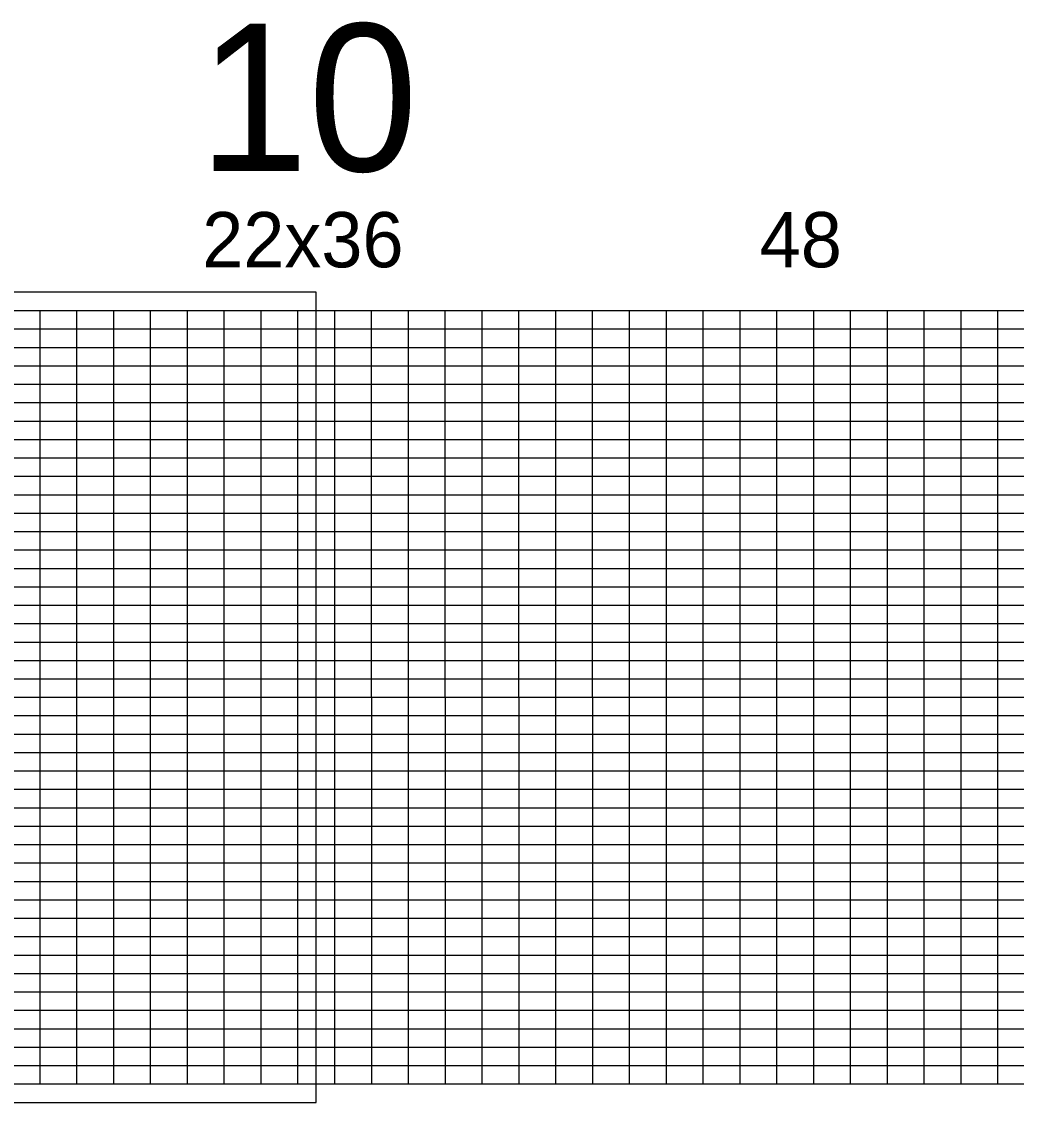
# Model space of a CAD drawing. Extents: x 1870112 to 1888282, y 758439 to 777406.
# Drawn here: x 1884257 to 1885607, y 758439 to 759906 of the extents above; entities that cross this region are included whole.
import ezdxf

# ---------------------------------------------------------------- set-up
doc = ezdxf.new("R2010")
doc.units = 0
for name, color, linetype in [('RD_PD_WallFill', 7, 'Continuous'), ('RD_SHT_IplotShp', 7, 'Continuous'), ('RD_Sketch8', 7, 'Continuous')]:
    doc.layers.add(name, color=color, linetype=linetype)

msp = doc.modelspace()

# ---------------------------------------------------------------- linework, layer by layer
at = {"layer": 'RD_PD_WallFill'}
for p, q in [((1882931.6, 759514.2), (1888281.6, 759514.2)), ((1882931.6, 759514.2), (1884681.6, 759514.2)), ((1884281.6, 758464.2), (1884281.6, 759514.2)), ((1884281.6, 758464.2), (1884281.6, 759514.2)), ((1884331.7, 758464.2), (1884331.6, 759514.2)), ((1884331.7, 758464.2), (1884331.6, 759514.2)), ((1884381.7, 758464.2), (1884381.6, 759514.2)), ((1884381.7, 758464.2), (1884381.6, 759514.2)), ((1884431.6, 758464.2), (1884431.7, 759514.2)), ((1884431.6, 758464.2), (1884431.7, 759514.2)), ((1884481.6, 758464.2), (1884481.6, 759514.2)), ((1884481.6, 758464.2), (1884481.6, 759514.2)), ((1884531.7, 758464.2), (1884531.6, 759514.2)), ((1884531.7, 758464.2), (1884531.6, 759514.2)), ((1884581.6, 758464.2), (1884581.7, 759514.2)), ((1884581.6, 758464.2), (1884581.7, 759514.2)), ((1884631.6, 758464.2), (1884631.7, 759514.2)), ((1884631.6, 758464.2), (1884631.7, 759514.2)), ((1884681.7, 758464.2), (1884681.6, 759514.2)), ((1884681.7, 758464.2), (1884681.6, 759514.2)), ((1884731.7, 758464.2), (1884731.6, 759514.2)), ((1884731.7, 758464.2), (1884731.6, 759514.2)), ((1884781.7, 758464.2), (1884781.6, 759514.2)), ((1884781.7, 758464.2), (1884781.6, 759514.2)), ((1884831.7, 758464.2), (1884831.6, 759514.2)), ((1884831.7, 758464.2), (1884831.6, 759514.2)), ((1884881.7, 758464.2), (1884881.6, 759514.2)), ((1884881.7, 758464.2), (1884881.6, 759514.2)), ((1884931.7, 758464.2), (1884931.6, 759514.2)), ((1884931.7, 758464.2), (1884931.6, 759514.2)), ((1884981.7, 758464.2), (1884981.6, 759514.2)), ((1884981.7, 758464.2), (1884981.6, 759514.2)), ((1885031.7, 758464.2), (1885031.6, 759514.2)), ((1885031.7, 758464.2), (1885031.6, 759514.2)), ((1885081.7, 758464.2), (1885081.6, 759514.2)), ((1885081.7, 758464.2), (1885081.6, 759514.2)), ((1885131.7, 758464.2), (1885131.6, 759514.2)), ((1885131.7, 758464.2), (1885131.6, 759514.2)), ((1885181.7, 758464.2), (1885181.6, 759514.2)), ((1885181.7, 758464.2), (1885181.6, 759514.2)), ((1885231.7, 758464.2), (1885231.6, 759514.2)), ((1885231.7, 758464.2), (1885231.6, 759514.2)), ((1885281.7, 758464.2), (1885281.6, 759514.2)), ((1885281.7, 758464.2), (1885281.6, 759514.2)), ((1885331.7, 758464.2), (1885331.6, 759514.2)), ((1885331.7, 758464.2), (1885331.6, 759514.2)), ((1885381.7, 758464.2), (1885381.6, 759514.2)), ((1885381.7, 758464.2), (1885381.6, 759514.2)), ((1885431.7, 758464.2), (1885431.6, 759514.2)), ((1885431.7, 758464.2), (1885431.6, 759514.2)), ((1885481.7, 758464.2), (1885481.6, 759514.2)), ((1885481.7, 758464.2), (1885481.6, 759514.2)), ((1885531.7, 758464.2), (1885531.6, 759514.2)), ((1885531.7, 758464.2), (1885531.6, 759514.2)), ((1885581.7, 758464.2), (1885581.6, 759514.2)), ((1885581.7, 758464.2), (1885581.6, 759514.2)), ((1883381.6, 759489.2), (1888281.6, 759489.2)), ((1883381.6, 759489.2), (1888281.6, 759489.2)), ((1883381.6, 759464.2), (1888281.6, 759464.2)), ((1883381.6, 759439.2), (1888281.6, 759439.2)), ((1883381.6, 759414.2), (1888281.6, 759414.2)), ((1883381.6, 759389.2), (1888281.6, 759389.2)), ((1882931.6, 759364.2), (1888281.6, 759364.2)), ((1882931.6, 759339.2), (1888281.6, 759339.2)), ((1882931.6, 759314.2), (1888281.6, 759314.2)), ((1882931.6, 759289.2), (1888281.6, 759289.2)), ((1882931.6, 759264.2), (1888281.6, 759264.2)), ((1882931.6, 759239.2), (1888281.6, 759239.2)), ((1882931.6, 759214.2), (1888281.6, 759214.2)), ((1882931.6, 759189.2), (1888281.6, 759189.2)), ((1882931.6, 759164.2), (1888281.6, 759164.2)), ((1882931.6, 759139.2), (1888281.6, 759139.2)), ((1882931.6, 759114.2), (1888281.6, 759114.2)), ((1882931.6, 759089.2), (1888281.6, 759089.2)), ((1882931.6, 759064.2), (1888281.6, 759064.2)), ((1882931.6, 759039.2), (1888281.6, 759039.2)), ((1882931.6, 759014.2), (1888281.6, 759014.2)), ((1882931.6, 758989.2), (1888281.6, 758989.2)), ((1882931.6, 758964.2), (1888281.6, 758964.2)), ((1882931.6, 758939.2), (1888281.6, 758939.2)), ((1882931.6, 758914.2), (1888281.6, 758914.2)), ((1882931.6, 758889.2), (1888281.6, 758889.2)), ((1882931.6, 758864.2), (1888281.6, 758864.2)), ((1882931.6, 758839.2), (1888281.6, 758839.2)), ((1882931.6, 758814.2), (1888281.6, 758814.2)), ((1882931.6, 758789.2), (1888281.6, 758789.2)), ((1882931.6, 758764.2), (1888281.6, 758764.2)), ((1882931.6, 758739.2), (1888281.6, 758739.2)), ((1882931.6, 758714.2), (1888281.6, 758714.2)), ((1882931.6, 758689.2), (1888281.6, 758689.2)), ((1882931.6, 758664.2), (1888281.6, 758664.2)), ((1882931.6, 758639.2), (1888281.6, 758639.2)), ((1882931.6, 758614.2), (1888281.6, 758614.2)), ((1882931.6, 758589.2), (1888281.6, 758589.2)), ((1882931.6, 758564.2), (1888281.6, 758564.2)), ((1882931.6, 758539.2), (1888281.6, 758539.2)), ((1882931.6, 758514.2), (1888281.6, 758514.2)), ((1882931.6, 758489.2), (1888281.6, 758489.2)), ((1882931.6, 758464.2), (1888281.6, 758464.2)), ((1882931.6, 758464.2), (1888281.6, 758464.2))]:
    msp.add_line(p, q, dxfattribs=at)
at = {"layer": 'RD_SHT_IplotShp'}
msp.add_lwpolyline([(1882906.6, 758439.2), (1884656.6, 758439.2), (1884656.6, 759539.2), (1882906.6, 759539.2)], close=True, dxfattribs=at)

# ---------------------------------------------------------------- texts
at = {"layer": 'RD_PD_WallFill'}
for s, p in [('22x36', (1884501.7, 759572.9)), ('22x36', (1884501.7, 759572.9)), ('48', (1885258.3, 759572.9)), ('48', (1885258.3, 759572.9))]:
    msp.add_text(s, height=75, dxfattribs=at).set_placement(p)
at = {"layer": 'RD_Sketch8'}
msp.add_text('10', height=200, dxfattribs=at).set_placement((1884496.9, 759703.5))

doc.saveas('drawing.dxf')
